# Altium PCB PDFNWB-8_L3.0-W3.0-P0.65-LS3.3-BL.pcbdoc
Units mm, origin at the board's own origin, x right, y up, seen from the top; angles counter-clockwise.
Board outline 15.85 x 16.61 mm, 2 copper layers (Top Layer, Bottom Layer), stack 0 mm thick; 1 components, 0 nets, 10 pads, 0 vias.
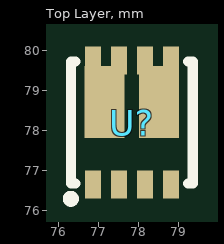
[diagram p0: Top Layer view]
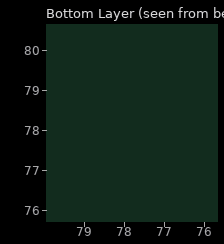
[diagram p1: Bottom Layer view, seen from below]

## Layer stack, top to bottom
Top Layer: signal copper (thickness not stored)
Bottom Layer: signal copper (thickness not stored)

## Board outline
85.698,69.85 69.85,69.85 69.85,86.455 85.698,86.455

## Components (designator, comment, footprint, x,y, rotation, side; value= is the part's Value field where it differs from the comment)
U? "" PDFNWB-8_L3.0-W3.0-P0.65-LS3.3-BL 77.824,78.205 r0 top

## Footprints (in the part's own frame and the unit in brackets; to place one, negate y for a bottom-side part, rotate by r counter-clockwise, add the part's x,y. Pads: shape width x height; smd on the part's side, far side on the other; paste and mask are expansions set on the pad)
PDFNWB-8_L3.0-W3.0-P0.65-LS3.3-BL [mm]
  rect 0.4x0.7 smd paste-100 mask+0.05: 1(-0.975,-1.55) 2(-0.325,-1.55) 3(0.325,-1.55) 4(0.975,-1.55) 5(0.975,1.55) 6(0.325,1.55) 7(-0.325,1.55) 8(-0.975,1.55)
  rect 1x1.8 smd paste-100 mask+0.05: 6(0.68,0.515) 8(-0.68,0.515)
  silkscreen extent -1.62,-2 1.52,1.52

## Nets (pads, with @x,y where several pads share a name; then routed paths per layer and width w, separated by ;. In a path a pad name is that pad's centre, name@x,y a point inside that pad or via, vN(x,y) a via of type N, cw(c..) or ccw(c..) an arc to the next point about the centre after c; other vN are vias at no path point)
pads on no net: U?.1 U?.2 U?.3 U?.4 U?.5 U?.6 U?.7 U?.8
